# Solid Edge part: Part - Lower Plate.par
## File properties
Author: hhakima
Template: Normal.par
Last saved by: hhakima
Revision: 35
Application: Solid Edge
Material: Aluminum, 6061-T6
Face Style: Aluminum
Fill Style: ANSI38(Aluminum)
Virtual Style: Polished aluminum
Coef. of Thermal Exp: 2.3e-05
Thermal Conductivity: 180.0
Specific Heat: 920.0
Modulus of Elasticity: 68947570000.0
Poission's Ratio: 0.33
Yield Stress: 275790280.0
Ultimate Stress: 310264065.0
Elongation: 0.0
Density: 2712.000 kg/m^3
Accuracy: 0.990
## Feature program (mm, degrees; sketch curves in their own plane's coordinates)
sketch for "unnamed Protrusion 1" plane through (0, 0, 0) normal (0, 0, 1) x-axis (1, 0, 0)
  line (-34.0498, 36.268) -> (15.9502, 36.268)
  line (15.9502, 36.268) -> (15.9502, 144.268)
  line (15.9502, 144.268) -> (-34.0498, 144.268)
  line (-34.0498, 144.268) -> (-34.0498, 36.268)
extrude "unnamed Protrusion 1" add finite 3 along +normal
sketch for "ExtrudedProtrusion_2" plane through (-14.5498, 62.268, 3) normal (0, 0, 1) x-axis (1, 0, 0)
  line (30.5, 82) -> (30.5, -26)
  line (30.5, -26) -> (33.5, -26)
  line (33.5, -26) -> (33.5, 82)
  line (33.5, 82) -> (30.5, 82)
  dimension (linear) = 33.5
  dimension (linear) = 33.5
extrude "ExtrudedProtrusion_2" add finite 35 along -normal
sketch for "ExtrudedProtrusion_4" #1 plane through (5.9502, 62.268, -32) normal (0, 0, -1) x-axis (0, 1, 0)
  line (8, 13) -> (13.5, 13)
  line (13.5, 13) -> (13.5, 18)
  line (13.5, 18) -> (8, 18)
  line (8, 18) -> (8, 13)
sketch for "ExtrudedProtrusion_4" #2 plane through (5.9502, 62.268, -32) normal (0, 0, -1) x-axis (0, 1, 0)
  line (42.5, 13) -> (48, 13)
  line (48, 13) -> (48, 18)
  line (48, 18) -> (42.5, 18)
  line (42.5, 18) -> (42.5, 13)
sketch for "ExtrudedProtrusion_4" #3 plane through (5.9502, 62.268, -32) normal (0, 0, -1) x-axis (0, 1, 0)
  line (77, 13) -> (82, 13)
  line (82, 13) -> (82, 18)
  line (82, 18) -> (77, 18)
  line (77, 18) -> (77, 13)
sketch for "ExtrudedProtrusion_4" #4 plane through (5.9502, 62.268, -32) normal (0, 0, -1) x-axis (0, 1, 0)
  line (-26, 13) -> (-21, 13)
  line (-21, 13) -> (-21, 18)
  line (-21, 18) -> (-26, 18)
  line (-26, 18) -> (-26, 13)
  dimension (linear) = 21
  dimension (linear) = 21
extrude "ExtrudedProtrusion_4" add finite 2 along -normal
sketch for "unnamed Hole 1" plane through (8.4502, 62.268, -32) normal (0, 0, -1) x-axis (0, 1, 0)
  hole centre (10.75, 13) bore radius 0.7835
hole "unnamed Hole 1" through
sketch for "unnamed Hole 2" plane through (8.4502, 62.268, -32) normal (0, 0, -1) x-axis (0, 1, 0)
  hole centre (45.25, 13) bore radius 0.7835
hole "unnamed Hole 2" through
sketch for "unnamed Hole 3" plane through (8.4502, 62.268, -32) normal (0, 0, -1) x-axis (0, 1, 0)
  hole centre (79.5, 13) bore radius 0.7835
hole "unnamed Hole 3" through
sketch for "unnamed Hole 4" plane through (8.4502, 62.268, -32) normal (0, 0, -1) x-axis (0, 1, 0)
  hole centre (-23.5, 13) bore radius 0.7835
  dimension (linear) = 23.5
  dimension (linear) = 23.5
hole "unnamed Hole 4" through
pattern "unnamed Pattern 1" of "unnamed Hole 1", "unnamed Hole 2", "unnamed Hole 3", "unnamed Hole 4"
mirror "unnamed Mirror 1" of "ExtrudedProtrusion_2", "ExtrudedProtrusion_4", "unnamed Pattern 1" about plane through (-9.0498, 62.268, 1) normal (1, 0, 0)
extrude "unnamed Protrusion 2" add finite 35
extrude "unnamed Protrusion 3" add finite 2
hole "unnamed Hole 5" through
hole "unnamed Hole 6" through
hole "unnamed Hole 7" through
hole "unnamed Hole 8" through
sketch for "unnamed Hole 9" plane through (-14.5498, 63.268, 0) normal (0, 0, -1) x-axis (1, 0, 0)
hole "unnamed Hole 9" through
sketch for "unnamed Hole 10" plane through (-14.5498, 63.268, 0) normal (0, 0, -1) x-axis (1, 0, 0)
  hole centre (-11.3, -76) bore radius 0.6105
  dimension (linear) = 11.3
  dimension (linear) = 11.3
hole "unnamed Hole 10" through
sketch for "ExtrudedProtrusion_8" #1 plane through (-14.5498, 144.268, -15.5) normal (0, 1, 0) x-axis (1, 0, 0)
  line (33.5, -18.5) -> (38.5, -18.5)
  line (38.5, -18.5) -> (38.5, -13.5)
  line (38.5, -13.5) -> (33.5, -13.5)
  line (33.5, -13.5) -> (33.5, -18.5)
sketch for "ExtrudedProtrusion_8" #2 plane through (-14.5498, 144.268, -15.5) normal (0, 1, 0) x-axis (1, 0, 0)
extrude "ExtrudedProtrusion_8" add finite 2 along -normal
mirror "unnamed Mirror 2" of "ExtrudedProtrusion_8" about plane through (-14.5498, 90.268, -13) normal (0, 1, 0)
extrude "unnamed Protrusion 4" add finite 2
sketch for "unnamed Hole 11" plane through (-14.5498, 36.268, -13) normal (0, -1, 0) x-axis (-1, 0, 0)
hole "unnamed Hole 11" through
sketch for "unnamed Hole 12" plane through (-14.5498, 36.268, -13) normal (0, -1, 0) x-axis (-1, 0, 0)
hole "unnamed Hole 12" through
pattern "unnamed Pattern 2" of "unnamed Hole 11", "unnamed Hole 12"
mirror "unnamed Mirror 3" of "unnamed Pattern 2" about plane through (-14.5498, 90.268, -13) normal (0, 1, 0)
pattern "unnamed Pattern 4"
hole "unnamed Hole 13" through
hole "unnamed Hole 14" through
sketch for "ExtrudedCutout_1" #1 plane through (18.9502, 90.268, -14.5) normal (1, 0, 0) x-axis (0, -1, 0)
  line (-54, -9.5) -> (-2, -9.5)
  line (-2, -9.5) -> (-2, -8.5)
  line (-2, -8.5) -> (-54, -8.5)
  line (-54, -8.5) -> (-54, -9.5)
sketch for "ExtrudedCutout_1" #2 plane through (18.9502, 90.268, -14.5) normal (1, 0, 0) x-axis (0, -1, 0)
  line (-54, -7.5) -> (-2, -7.5)
  line (-2, -7.5) -> (-2, -6.5)
  line (-2, -6.5) -> (-54, -6.5)
  line (-54, -6.5) -> (-54, -7.5)
sketch for "ExtrudedCutout_1" #3 plane through (18.9502, 90.268, -14.5) normal (1, 0, 0) x-axis (0, -1, 0)
  line (-54, -5.5) -> (-2, -5.5)
  line (-2, -5.5) -> (-2, -4.5)
  line (-2, -4.5) -> (-54, -4.5)
  line (-54, -4.5) -> (-54, -5.5)
sketch for "ExtrudedCutout_1" #4 plane through (18.9502, 90.268, -14.5) normal (1, 0, 0) x-axis (0, -1, 0)
  line (-54, -3.5) -> (-2, -3.5)
  line (-2, -3.5) -> (-2, -2.5)
  line (-2, -2.5) -> (-54, -2.5)
  line (-54, -2.5) -> (-54, -3.5)
sketch for "ExtrudedCutout_1" #5 plane through (18.9502, 90.268, -14.5) normal (1, 0, 0) x-axis (0, -1, 0)
  line (-54, -1.5) -> (-2, -1.5)
  line (-2, -1.5) -> (-2, -0.5)
  line (-2, -0.5) -> (-54, -0.5)
  line (-54, -0.5) -> (-54, -1.5)
sketch for "ExtrudedCutout_1" #6 plane through (18.9502, 90.268, -14.5) normal (1, 0, 0) x-axis (0, -1, 0)
  line (-54, 0.5) -> (-2, 0.5)
  line (-2, 0.5) -> (-2, 1.5)
  line (-2, 1.5) -> (-54, 1.5)
  line (-54, 1.5) -> (-54, 0.5)
sketch for "ExtrudedCutout_1" #7 plane through (18.9502, 90.268, -14.5) normal (1, 0, 0) x-axis (0, -1, 0)
  line (-54, 2.5) -> (-2, 2.5)
  line (-2, 2.5) -> (-2, 3.5)
  line (-2, 3.5) -> (-54, 3.5)
  line (-54, 3.5) -> (-54, 2.5)
sketch for "ExtrudedCutout_1" #8 plane through (18.9502, 90.268, -14.5) normal (1, 0, 0) x-axis (0, -1, 0)
  line (-54, 6.5) -> (-2, 6.5)
  line (-2, 6.5) -> (-2, 7.5)
  line (-2, 7.5) -> (-54, 7.5)
  line (-54, 7.5) -> (-54, 6.5)
sketch for "ExtrudedCutout_1" #9 plane through (18.9502, 90.268, -14.5) normal (1, 0, 0) x-axis (0, -1, 0)
  line (-54, 8.5) -> (-2, 8.5)
  line (-2, 8.5) -> (-2, 9.5)
  line (-2, 9.5) -> (-54, 9.5)
  line (-54, 9.5) -> (-54, 8.5)
sketch for "ExtrudedCutout_1" #10 plane through (18.9502, 90.268, -14.5) normal (1, 0, 0) x-axis (0, -1, 0)
  line (-54, 4.5) -> (-2, 4.5)
  line (-2, 4.5) -> (-2, 5.5)
  line (-2, 5.5) -> (-54, 5.5)
  line (-54, 5.5) -> (-54, 4.5)
sketch for "ExtrudedCutout_1" #11 plane through (18.9502, 90.268, -14.5) normal (1, 0, 0) x-axis (0, -1, 0)
  line (-54, 10.5) -> (-2, 10.5)
  line (-2, 10.5) -> (-2, 11.5)
  line (-2, 11.5) -> (-54, 11.5)
  line (-54, 11.5) -> (-54, 10.5)
sketch for "ExtrudedCutout_1" #12 plane through (18.9502, 90.268, -14.5) normal (1, 0, 0) x-axis (0, -1, 0)
  line (-54, 12.5) -> (-2, 12.5)
  line (-2, 12.5) -> (-2, 13.5)
  line (-2, 13.5) -> (-54, 13.5)
  line (-54, 13.5) -> (-54, 12.5)
sketch for "ExtrudedCutout_1" #13 plane through (18.9502, 90.268, -14.5) normal (1, 0, 0) x-axis (0, -1, 0)
extrude "ExtrudedCutout_1" cut finite 1 along -normal
mirror "unnamed Mirror 4" of "ExtrudedCutout_1" about plane through (-14.5498, 90.268, -13) normal (0, 1, 0)
extrude "unnamed Cutout 1" cut finite 1
mirror "unnamed Mirror 5" of "ExtrudedCutout_1", "unnamed Mirror 4" about plane through (-9.0498, 62.268, 1) normal (1, 0, 0)
extrude "unnamed Cutout 2" cut finite 1
extrude "unnamed Cutout 3" cut finite 1
pattern "unnamed Pattern 5" of "unnamed Hole 9", "unnamed Hole 10"
pattern "unnamed Pattern 3" of "unnamed Pattern 5"
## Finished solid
Body 1: solid body, 274 faces, 800 edges, 512 vertices.
  Faces by surface: plane 258, cylinder 16
  Edges by curve: line 768, circle 32
Bounding box of the edges (mm): 66.000 x 108.000 x 35.000, from (-42.0498, 36.268, -32) to (23.9502, 144.268, 3).
Cylindrical faces by radius (mm): R0.6105 x4, R0.7835 x12
Planar faces by outward normal: +x 34, +y 35, +z 61, -x 34, -y 35, -z 59
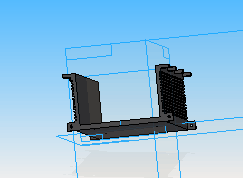
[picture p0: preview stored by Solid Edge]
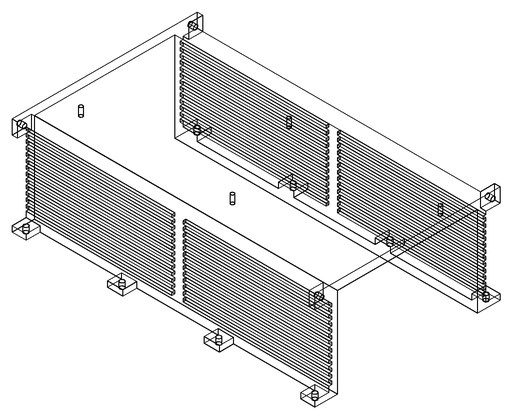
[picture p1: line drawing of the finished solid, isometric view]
